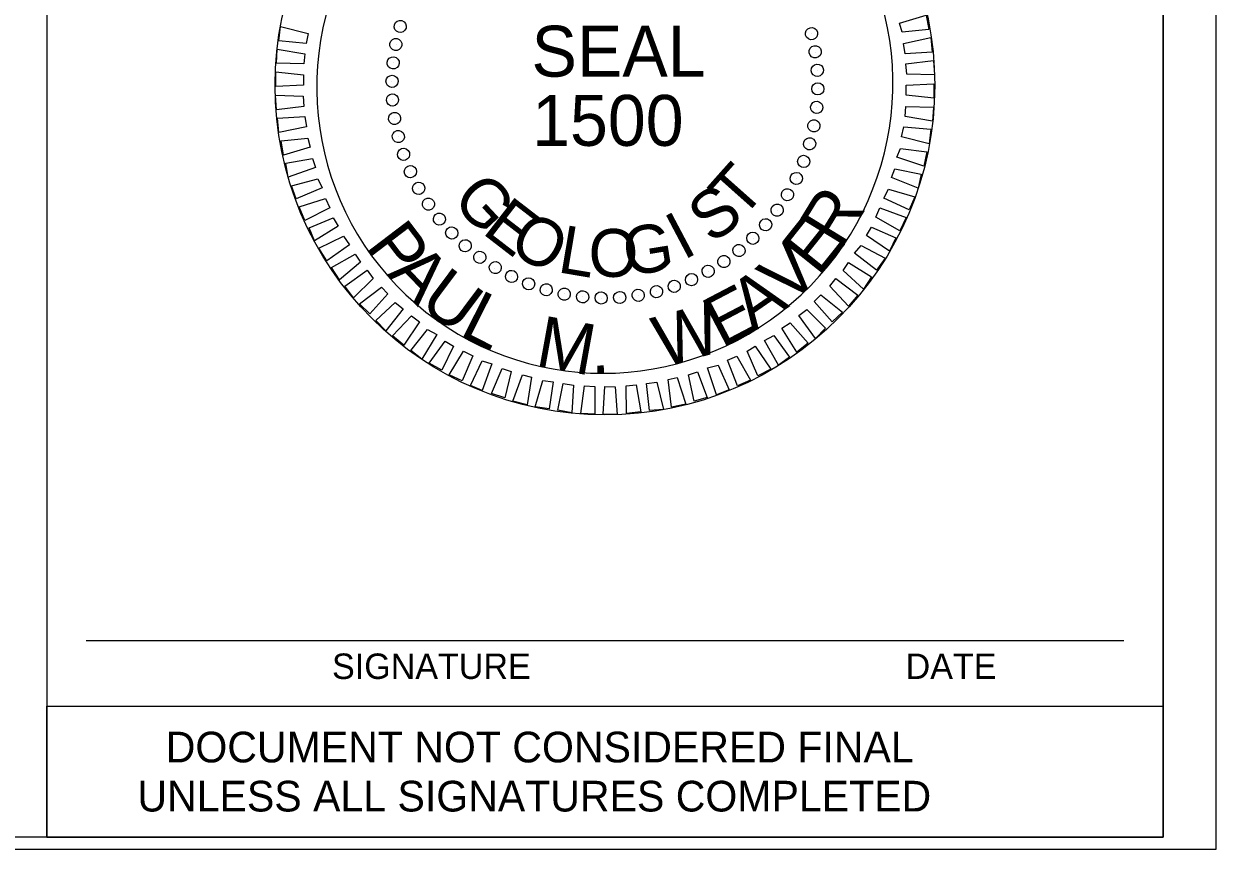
# Model space of a CAD drawing. Extents: x 265553 to 275568, y 168312 to 173522.
# Drawn here: x 268190.7 to 268471.5, y 172139.7 to 172334.2 of the extents above; entities that cross this region are included whole.
import ezdxf

# ---------------------------------------------------------------- set-up
doc = ezdxf.new("R2010")
doc.units = 0
for name, color, linetype in [('Geotech Sheets and Borders Cell', 7, 'Continuous'), ('Scratch_Level_0', 7, 'Continuous'), ('Scratch_Level_6', 7, 'Continuous'), ('Sheet Plot Border Inside CELL', 7, 'Continuous'), ('Sheet Professional Seal CELL', 7, 'Continuous'), ('Sheet Sticker Exception Certification CELL', 7, 'Continuous')]:
    doc.layers.add(name, color=color, linetype=linetype)

msp = doc.modelspace()

# ---------------------------------------------------------------- linework, layer by layer
at = {"layer": 'Geotech Sheets and Borders Cell'}
msp.add_line((268449.74, 172188.86), (268205.32, 172188.86), dxfattribs=at)
msp.add_lwpolyline([(266959.02, 173192.58), (268459.02, 173192.58), (268459.02, 172142.58), (266959.02, 172142.58)], close=True, dxfattribs=at)
msp.add_lwpolyline([(268459.02, 172420.84), (268459.02, 172420.84), (268196.05, 172420.84), (268196.05, 172142.58), (268459.02, 172142.58), (268459.02, 172420.84)], dxfattribs=at)
at = {"layer": 'Scratch_Level_0'}
msp.add_ellipse((268327.53, 172319.79), major_axis=(45.09, 51.04), ratio=0.993455, start_param=1.731198, end_param=5.992706, dxfattribs=at)
at = {"layer": 'Scratch_Level_6'}
msp.add_circle((268327.53, 172319.79), 77.7, dxfattribs=at)
msp.add_circle((268327.53, 172319.79), 77.7, dxfattribs=at)
at = {"layer": 'Sheet Plot Border Inside CELL'}
msp.add_lwpolyline([(266803.85, 172139.74), (268471.52, 172139.74), (268471.52, 173195.41), (266803.85, 173195.41)], close=True, dxfattribs=at)
at = {"layer": 'Sheet Professional Seal CELL'}
for p, q in [((268279.23, 172333.59), (268279.23, 172333.59)), ((268376.23, 172331.99), (268376.23, 172331.99)), ((268278.33, 172329.39), (268278.33, 172329.39)), ((268377.03, 172327.59), (268377.03, 172327.59)), ((268277.63, 172325.09), (268277.63, 172325.09)), ((268377.63, 172323.29), (268377.63, 172323.29)), ((268277.33, 172320.69), (268277.33, 172320.69)), ((268377.73, 172318.89), (268377.73, 172318.89)), ((268277.43, 172316.29), (268277.43, 172316.29)), ((268377.43, 172314.49), (268377.43, 172314.49)), ((268278.03, 172311.99), (268278.03, 172311.99)), ((268376.73, 172310.19), (268376.73, 172310.19)), ((268278.83, 172307.59), (268278.83, 172307.59)), ((268375.83, 172305.99), (268375.83, 172305.99)), ((268280.03, 172303.39), (268280.03, 172303.39)), ((268374.43, 172301.79), (268374.43, 172301.79)), ((268281.63, 172299.39), (268281.63, 172299.39)), ((268372.63, 172297.79), (268372.63, 172297.79)), ((268283.63, 172295.49), (268283.63, 172295.49)), ((268370.63, 172293.89), (268370.63, 172293.89)), ((268285.93, 172291.69), (268285.93, 172291.69)), ((268288.43, 172288.19), (268288.43, 172288.19)), ((268368.13, 172290.29), (268368.13, 172290.29)), ((268291.43, 172284.89), (268291.43, 172284.89)), ((268365.43, 172286.79), (268365.43, 172286.79)), ((268362.43, 172283.69), (268362.43, 172283.69)), ((268294.53, 172281.89), (268294.53, 172281.89)), ((268359.13, 172280.69), (268359.13, 172280.69)), ((268298.03, 172279.19), (268298.03, 172279.19)), ((268301.63, 172276.69), (268301.63, 172276.69)), ((268355.63, 172278.19), (268355.63, 172278.19)), ((268305.53, 172274.69), (268305.53, 172274.69)), ((268347.93, 172273.89), (268347.93, 172273.89)), ((268351.83, 172275.89), (268351.83, 172275.89)), ((268309.53, 172272.89), (268309.53, 172272.89)), ((268313.73, 172271.49), (268313.73, 172271.49)), ((268339.73, 172271.09), (268339.73, 172271.09)), ((268343.93, 172272.29), (268343.93, 172272.29)), ((268317.93, 172270.59), (268317.93, 172270.59)), ((268322.23, 172269.89), (268322.23, 172269.89)), ((268326.63, 172269.59), (268326.63, 172269.59)), ((268331.03, 172269.69), (268331.03, 172269.69)), ((268335.33, 172270.29), (268335.33, 172270.29))]:
    msp.add_line(p, q, dxfattribs=at)
for points in [[(268396.93, 172334.39), (268403.23, 172336.29), (268403.83, 172332.89), (268397.53, 172332.29)], [(268257.13, 172329.59), (268250.73, 172330.19), (268251.13, 172333.59), (268257.63, 172331.99)], [(268397.83, 172329.59), (268404.33, 172330.99), (268404.63, 172327.59), (268398.23, 172327.19)], [(268256.63, 172324.79), (268250.13, 172324.99), (268250.33, 172328.29), (268256.83, 172327.19)], [(268398.43, 172324.79), (268404.93, 172325.59), (268405.13, 172322.19), (268398.63, 172322.39)], [(268256.53, 172319.79), (268250.03, 172319.49), (268250.03, 172322.89), (268256.53, 172322.19)], [(268398.53, 172319.79), (268405.03, 172320.09), (268405.03, 172316.69), (268398.53, 172317.39)], [(268256.63, 172314.79), (268250.13, 172313.99), (268249.93, 172317.39), (268256.43, 172317.19)], [(268398.43, 172314.79), (268404.93, 172314.59), (268404.73, 172311.29), (268398.23, 172312.39)], [(268257.23, 172309.99), (268250.73, 172308.59), (268250.43, 172311.99), (268256.83, 172312.39)], [(268397.93, 172309.99), (268404.33, 172309.39), (268403.93, 172305.99), (268397.43, 172307.59)], [(268258.13, 172305.19), (268251.83, 172303.29), (268251.23, 172306.69), (268257.53, 172307.29)], [(268397.13, 172304.89), (268403.33, 172304.09), (268402.63, 172300.69), (268396.33, 172302.79)], [(268259.33, 172300.39), (268252.93, 172298.09), (268252.33, 172301.39), (268258.63, 172302.49)], [(268395.83, 172300.09), (268402.03, 172298.79), (268401.33, 172295.49), (268395.03, 172297.99)], [(268260.93, 172295.59), (268254.83, 172292.99), (268253.73, 172296.09), (268259.93, 172297.69)], [(268394.33, 172295.29), (268400.53, 172293.49), (268399.23, 172290.39), (268393.23, 172293.19)], [(268262.73, 172290.89), (268256.83, 172287.89), (268255.53, 172291.09), (268261.73, 172293.09)], [(268392.33, 172290.89), (268398.53, 172288.59), (268397.03, 172285.49), (268391.33, 172288.69)], [(268264.73, 172286.59), (268259.13, 172283.09), (268257.83, 172286.19), (268263.53, 172288.49)], [(268390.33, 172286.29), (268396.03, 172283.79), (268394.53, 172280.69), (268389.13, 172284.39)], [(268267.33, 172282.19), (268262.03, 172278.39), (268260.13, 172281.39), (268265.93, 172284.19)], [(268269.93, 172278.09), (268265.03, 172273.89), (268263.13, 172276.79), (268268.73, 172279.99)], [(268387.93, 172281.99), (268393.53, 172278.99), (268391.53, 172276.19), (268386.33, 172280.19)], [(268384.93, 172277.99), (268390.33, 172274.59), (268388.43, 172271.69), (268383.63, 172276.09)], [(268272.93, 172274.19), (268268.33, 172269.69), (268266.23, 172272.39), (268271.53, 172276.19)], [(268381.93, 172274.19), (268387.13, 172270.29), (268384.93, 172267.69), (268380.53, 172272.39)], [(268276.43, 172270.59), (268272.13, 172265.89), (268269.73, 172268.29), (268274.93, 172272.19)], [(268280.03, 172267.09), (268275.93, 172261.89), (268273.53, 172264.29), (268278.13, 172268.59)], [(268378.43, 172270.39), (268383.53, 172266.29), (268381.03, 172263.99), (268376.83, 172268.79)], [(268283.83, 172263.99), (268280.13, 172258.49), (268277.53, 172260.69), (268281.93, 172265.39)], [(268375.13, 172266.89), (268379.53, 172262.49), (268377.13, 172260.09), (268373.23, 172265.49)], [(268371.13, 172263.79), (268375.43, 172258.99), (268372.73, 172256.89), (268369.23, 172262.49)], [(268287.93, 172260.99), (268284.43, 172255.19), (268281.83, 172257.29), (268285.73, 172262.19)], [(268367.33, 172260.79), (268371.03, 172255.69), (268368.43, 172253.79), (268365.13, 172259.59)], [(268291.83, 172258.29), (268289.13, 172252.59), (268286.13, 172254.29), (268289.93, 172259.49)], [(268296.43, 172255.99), (268293.93, 172250.09), (268290.83, 172251.49), (268294.23, 172257.09)], [(268362.93, 172258.29), (268366.63, 172252.89), (268363.53, 172251.29), (268361.03, 172257.09)], [(268300.93, 172254.09), (268298.63, 172247.79), (268295.83, 172248.99), (268298.63, 172254.79)], [(268358.63, 172255.89), (268361.83, 172250.29), (268358.73, 172248.89), (268356.43, 172254.99)], [(268305.43, 172252.29), (268303.93, 172246.09), (268300.83, 172247.09), (268303.33, 172252.99)], [(268310.23, 172250.99), (268309.23, 172244.49), (268305.83, 172245.29), (268308.13, 172251.49)], [(268349.33, 172252.19), (268351.63, 172246.19), (268348.53, 172245.29), (268347.23, 172251.49)], [(268354.23, 172253.79), (268356.83, 172247.99), (268353.83, 172246.79), (268351.73, 172253.19)], [(268315.33, 172249.89), (268314.43, 172243.49), (268311.13, 172243.99), (268312.93, 172250.19)], [(268320.13, 172249.09), (268319.73, 172242.59), (268316.43, 172243.19), (268317.73, 172249.49)], [(268325.13, 172248.79), (268325.13, 172242.29), (268321.83, 172242.39), (268322.73, 172248.89)], [(268329.93, 172248.69), (268330.43, 172242.19), (268327.13, 172242.29), (268327.53, 172248.79)], [(268334.93, 172249.19), (268336.03, 172242.79), (268332.63, 172242.39), (268332.53, 172248.89)], [(268339.73, 172249.79), (268341.33, 172243.39), (268338.03, 172243.09), (268337.33, 172249.49)], [(268344.53, 172250.89), (268346.63, 172244.59), (268343.23, 172243.89), (268342.43, 172250.39)]]:
    msp.add_lwpolyline(points, close=True, dxfattribs=at)
for centre, major_axis in [((268279.32, 172333.62), (-1.38, 0.4)), ((268376.2, 172331.92), (1.4, 0.35)), ((268278.29, 172329.36), (-1.41, 0.27)), ((268377.07, 172327.64), (1.42, 0.23)), ((268277.65, 172325.03), (-1.43, 0.15)), ((268377.57, 172323.29), (1.44, 0.1)), ((268277.38, 172320.67), (-1.44, 0.03)), ((268377.68, 172318.91), (1.44, -0.03)), ((268277.49, 172316.29), (-1.44, -0.1)), ((268377.42, 172314.55), (1.43, -0.15)), ((268277.99, 172311.94), (-1.42, -0.23)), ((268376.77, 172310.22), (1.41, -0.27)), ((268278.86, 172307.66), (-1.4, -0.35)), ((268375.75, 172305.96), (1.38, -0.4)), ((268280.1, 172303.46), (-1.36, -0.47)), ((268374.36, 172301.81), (1.34, -0.52)), ((268281.71, 172299.39), (-1.32, -0.59)), ((268372.62, 172297.8), (1.29, -0.63)), ((268283.66, 172295.47), (-1.26, -0.7)), ((268285.95, 172291.74), (-1.19, -0.81)), ((268370.53, 172293.96), (1.23, -0.74)), ((268368.11, 172290.31), (1.16, -0.85)), ((268288.55, 172288.22), (-1.12, -0.91)), ((268365.39, 172286.88), (1.09, -0.94)), ((268291.45, 172284.95), (-1.04, -1)), ((268362.38, 172283.71), (1, -1.04)), ((268294.62, 172281.93), (-0.94, -1.09)), ((268359.1, 172280.81), (0.91, -1.12)), ((268298.05, 172279.21), (-0.85, -1.16)), ((268355.58, 172278.21), (0.81, -1.19)), ((268301.7, 172276.79), (-0.74, -1.23)), ((268351.85, 172275.92), (0.7, -1.26)), ((268305.54, 172274.71), (-0.63, -1.29)), ((268309.56, 172272.96), (-0.52, -1.34)), ((268343.86, 172272.36), (0.47, -1.36)), ((268347.93, 172273.97), (0.59, -1.32)), ((268313.71, 172271.57), (-0.4, -1.38)), ((268317.96, 172270.55), (-0.27, -1.41)), ((268322.29, 172269.9), (-0.15, -1.43)), ((268326.66, 172269.64), (-0.03, -1.44)), ((268331.03, 172269.75), (0.1, -1.44)), ((268335.38, 172270.25), (0.23, -1.42)), ((268339.67, 172271.12), (0.35, -1.4))]:
    msp.add_ellipse(centre, major_axis=major_axis, ratio=0.999708, dxfattribs=at)
at = {"layer": 'Sheet Sticker Exception Certification CELL'}
for p, q in [((268196.05, 172142.58), (268196.05, 172173.47)), ((268196.05, 172173.47), (268459.02, 172173.47)), ((268459.02, 172173.47), (268459.02, 172142.58)), ((268196.05, 172142.58), (268459.02, 172142.58))]:
    msp.add_line(p, q, dxfattribs=at)

# ---------------------------------------------------------------- texts
at = {"layer": 'Geotech Sheets and Borders Cell'}
for s, p in [('SIGNATURE', (268263.25, 172179.85)), ('DATE', (268398.37, 172179.85))]:
    msp.add_text(s, height=6, dxfattribs=at).set_placement(p)
at = {"layer": 'Sheet Professional Seal CELL'}
for s, p in [('SEAL', (268310.24, 172321.79)), ('1500', (268310.38, 172305.48))]:
    msp.add_text(s, height=11.996, dxfattribs=at).set_placement(p)
for s, height, rotation, p in [('T', 11.28, 48.3432, (268359.67, 172287.87)), ('G', 11.28, 312.9799, (268291.18, 172292.51)), ('S', 11.28, 37.1844, (268352.75, 172282.15)), ('R', 12, 58.4746, (268383.11, 172280.97)), ('E', 11.28, 322.3369, (268298.35, 172285.03)), ('P', 12, 307.2789, (268270.93, 172281.74)), ('O', 11.28, 331.6932, (268304.39, 172280.65)), ('I', 11.28, 27.8271, (268345.99, 172278.43)), ('E', 12, 51.4825, (268377.89, 172274.42)), ('L', 11.28, 350.4042, (268316.12, 172275.75)), ('O', 11.28, 359.7594, (268323.65, 172274.63)), ('G', 11.28, 9.1148, (268332.75, 172274.72)), ('V', 12, 43.3675, (268370.89, 172267.68)), ('A', 12, 314.4055, (268276, 172275.08)), ('U', 12, 323.2702, (268283.4, 172267.76)), ('A', 12, 34.6703, (268362.42, 172261.63)), ('L', 12, 333.2297, (268292.94, 172260.99)), ('E', 12, 27.6676, (268355.01, 172257.74)), ('W', 12, 15.2925, (268340.98, 172253.19)), ('M', 12, 349.7003, (268310.88, 172253.72)), ('.', 12, 1.1804, (268324.31, 172251.81))]:
    msp.add_text(s, height=height, rotation=rotation, dxfattribs=at).set_placement(p)
at = {"layer": 'Sheet Sticker Exception Certification CELL'}
for s, p in [('DOCUMENT NOT CONSIDERED FINAL', (268224.08, 172160.19)), ('UNLESS ALL SIGNATURES COMPLETED', (268217.41, 172148.62))]:
    msp.add_text(s, height=7.2302, dxfattribs=at).set_placement(p)

doc.saveas('drawing.dxf')
